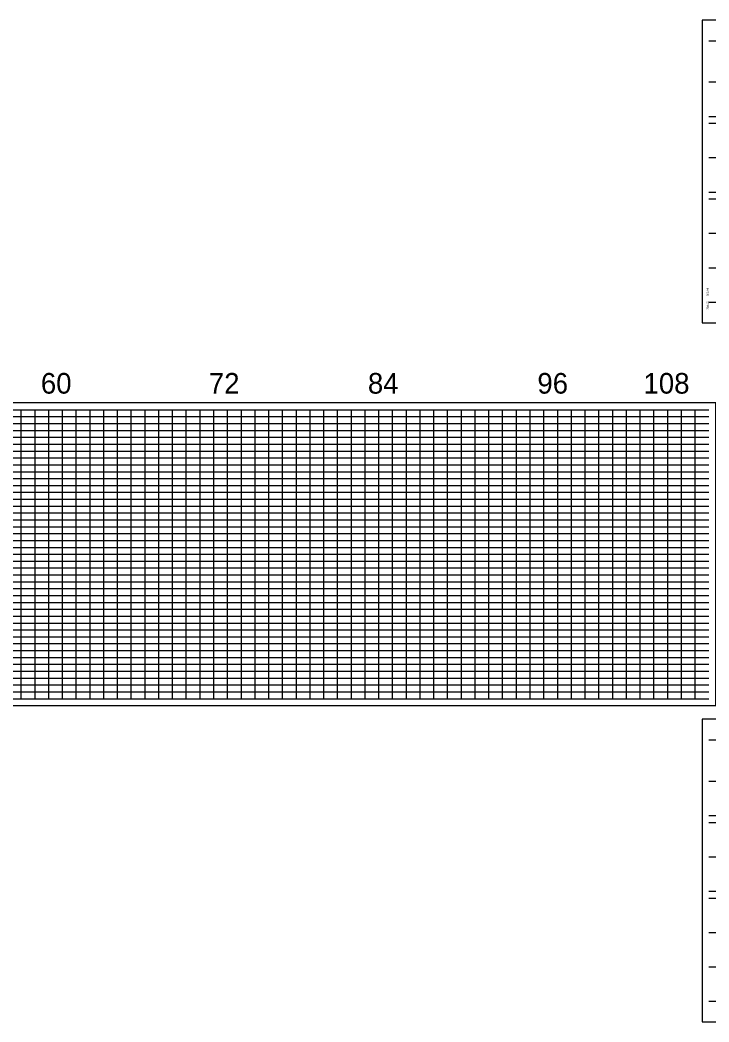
# Model space of a CAD drawing. Extents: x 1873632 to 1926512, y 813126 to 836257.
# Drawn here: x 1897209 to 1899713, y 823217 to 826858 of the extents above; entities that cross this region are included whole.
import ezdxf

# ---------------------------------------------------------------- set-up
doc = ezdxf.new("R2010")
doc.units = 0
for name, color, linetype in [('RD_DDB_StripGrade', 7, 'Continuous'), ('RD_PD_WallFill', 7, 'Continuous'), ('RD_SHT_IplotShp', 7, 'Continuous')]:
    doc.layers.add(name, color=color, linetype=linetype)

msp = doc.modelspace()

# ---------------------------------------------------------------- linework, layer by layer
at = {"layer": 'RD_PD_WallFill'}
for p, q in [((1899713.1, 826783.1), (1899763.1, 826783.1)), ((1899713.1, 826783.1), (1899763.1, 826783.1)), ((1899713.1, 826633.1), (1905063.1, 826633.1)), ((1899713.1, 826508.1), (1905063.1, 826508.1)), ((1899713.1, 826483.1), (1905063.1, 826483.1)), ((1899713.1, 826358.1), (1905063.1, 826358.1)), ((1899713.1, 826233.1), (1905063.1, 826233.1)), ((1899713.1, 826208.1), (1905063.1, 826208.1)), ((1899713.1, 826083.1), (1905063.1, 826083.1)), ((1899713.1, 825958.1), (1905063.1, 825958.1)), ((1899713.1, 825833.1), (1905063.1, 825833.1)), ((1894363.1, 825441.6), (1899713.1, 825441.6)), ((1897213.1, 824391.6), (1897213.1, 825441.6)), ((1897213.1, 824391.6), (1897213.1, 825441.6)), ((1897263.1, 824391.6), (1897263.1, 825441.6)), ((1897263.1, 824391.6), (1897263.1, 825441.6)), ((1897313.1, 824391.6), (1897313.1, 825441.6)), ((1897313.1, 824391.6), (1897313.1, 825441.6)), ((1897363.1, 824391.6), (1897363.1, 825441.6)), ((1897363.1, 824391.6), (1897363.1, 825441.6)), ((1897413.1, 824391.6), (1897413.1, 825441.6)), ((1897413.1, 824391.6), (1897413.1, 825441.6)), ((1897463.1, 824391.6), (1897463.1, 825441.6)), ((1897463.1, 824391.6), (1897463.1, 825441.6)), ((1897513.1, 824391.6), (1897513.1, 825441.6)), ((1897513.1, 824391.6), (1897513.1, 825441.6)), ((1897563.1, 824391.6), (1897563.1, 825441.6)), ((1897563.1, 824391.6), (1897563.1, 825441.6)), ((1897613.1, 824391.6), (1897613.1, 825441.6)), ((1897613.1, 824391.6), (1897613.1, 825441.6)), ((1897663.1, 824391.6), (1897663.1, 825441.6)), ((1897663.1, 824391.6), (1897663.1, 825441.6)), ((1897713.1, 824391.6), (1897713.1, 825441.6)), ((1897713.1, 824391.6), (1897713.1, 825441.6)), ((1897763.1, 824391.6), (1897763.1, 825441.6)), ((1897763.1, 824391.6), (1897763.1, 825441.6)), ((1897813.1, 824391.6), (1897813.1, 825441.6)), ((1897813.1, 824391.6), (1897813.1, 825441.6)), ((1897863.1, 824391.6), (1897863.1, 825441.6)), ((1897863.1, 824391.6), (1897863.1, 825441.6)), ((1897913.1, 824391.6), (1897913.1, 825441.6)), ((1897913.1, 824391.6), (1897913.1, 825441.6)), ((1897963.1, 824391.6), (1897963.1, 825441.6)), ((1897963.1, 824391.6), (1897963.1, 825441.6)), ((1898013.1, 824391.6), (1898013.1, 825441.6)), ((1898013.1, 824391.6), (1898013.1, 825441.6)), ((1898063.1, 824391.6), (1898063.1, 825441.6)), ((1898063.1, 824391.6), (1898063.1, 825441.6)), ((1898113.1, 824391.6), (1898113.1, 825441.6)), ((1898113.1, 824391.6), (1898113.1, 825441.6)), ((1898163.1, 824391.6), (1898163.1, 825441.6)), ((1898163.1, 824391.6), (1898163.1, 825441.6)), ((1898213.1, 824391.6), (1898213.1, 825441.6)), ((1898213.1, 824391.6), (1898213.1, 825441.6)), ((1898263.1, 824391.6), (1898263.1, 825441.6)), ((1898263.1, 824391.6), (1898263.1, 825441.6)), ((1898313.1, 824391.6), (1898313.1, 825441.6)), ((1898313.1, 824391.6), (1898313.1, 825441.6)), ((1898363.1, 824391.6), (1898363.1, 825441.6)), ((1898363.1, 824391.6), (1898363.1, 825441.6)), ((1898413.1, 824391.6), (1898413.1, 825441.6)), ((1898413.1, 824391.6), (1898413.1, 825441.6)), ((1898463.1, 824391.6), (1898463.1, 825441.6)), ((1898463.1, 824391.6), (1898463.1, 825441.6)), ((1898513.1, 824391.6), (1898513.1, 825441.6)), ((1898513.1, 824391.6), (1898513.1, 825441.6)), ((1898563.1, 824391.6), (1898563.1, 825441.6)), ((1898563.1, 824391.6), (1898563.1, 825441.6)), ((1898613.1, 824391.6), (1898613.1, 825441.6)), ((1898613.1, 824391.6), (1898613.1, 825441.6)), ((1898663.1, 824391.6), (1898663.1, 825441.6)), ((1898663.1, 824391.6), (1898663.1, 825441.6)), ((1898713.1, 824391.6), (1898713.1, 825441.6)), ((1898713.1, 824391.6), (1898713.1, 825441.6)), ((1898763.1, 824391.6), (1898763.1, 825441.6)), ((1898763.1, 824391.6), (1898763.1, 825441.6)), ((1898813.1, 824391.6), (1898813.1, 825441.6)), ((1898813.1, 824391.6), (1898813.1, 825441.6)), ((1898863.1, 824391.6), (1898863.1, 825441.6)), ((1898863.1, 824391.6), (1898863.1, 825441.6)), ((1898913.1, 824391.6), (1898913.1, 825441.6)), ((1898913.1, 824391.6), (1898913.1, 825441.6)), ((1898963.1, 824391.6), (1898963.1, 825441.6)), ((1898963.1, 824391.6), (1898963.1, 825441.6)), ((1899013.1, 824391.6), (1899013.1, 825441.6)), ((1899013.1, 824391.6), (1899013.1, 825441.6)), ((1899063.1, 824391.6), (1899063.1, 825441.6)), ((1899063.1, 824391.6), (1899063.1, 825441.6)), ((1899113.1, 824391.6), (1899113.1, 825441.6)), ((1899113.1, 824391.6), (1899113.1, 825441.6)), ((1899163.1, 824391.6), (1899163.1, 825441.6)), ((1899163.1, 824391.6), (1899163.1, 825441.6)), ((1899213.1, 824391.6), (1899213.1, 825441.6)), ((1899213.1, 824391.6), (1899213.1, 825441.6)), ((1899263.1, 824391.6), (1899263.1, 825441.6)), ((1899263.1, 824391.6), (1899263.1, 825441.6)), ((1899313.1, 824391.6), (1899313.1, 825441.6)), ((1899313.1, 824391.6), (1899313.1, 825441.6)), ((1899363.1, 824391.6), (1899363.1, 825441.6)), ((1899363.1, 824391.6), (1899363.1, 825441.6)), ((1899413.1, 824391.6), (1899413.1, 825441.6)), ((1899413.1, 824391.6), (1899413.1, 825441.6)), ((1899463.1, 824391.6), (1899463.1, 825441.6)), ((1899463.1, 824391.6), (1899463.1, 825441.6)), ((1899513.2, 824391.6), (1899513.1, 825441.6)), ((1899513.2, 824391.6), (1899513.1, 825441.6)), ((1899563.1, 824391.6), (1899563.2, 825441.6)), ((1899563.1, 824391.6), (1899563.2, 825441.6)), ((1899613.1, 824391.6), (1899613.1, 825441.6)), ((1899613.1, 824391.6), (1899613.1, 825441.6)), ((1899663.1, 824391.6), (1899663.1, 825441.6)), ((1899663.1, 824391.6), (1899663.1, 825441.6)), ((1894813.1, 825416.6), (1899713.1, 825416.6)), ((1894813.1, 825416.6), (1899713.1, 825416.6)), ((1894813.1, 825391.6), (1899713.1, 825391.6)), ((1894813.1, 825366.6), (1899713.1, 825366.6)), ((1894813.1, 825341.6), (1899713.1, 825341.6)), ((1894813.1, 825316.6), (1899713.1, 825316.6)), ((1894363.1, 825291.6), (1899713.1, 825291.6)), ((1894363.1, 825266.6), (1899713.1, 825266.6)), ((1894363.1, 825241.6), (1899713.1, 825241.6)), ((1894363.1, 825216.6), (1899713.1, 825216.6)), ((1894363.1, 825191.6), (1899713.1, 825191.6)), ((1894363.1, 825166.6), (1899713.1, 825166.6)), ((1894363.1, 825141.6), (1899713.1, 825141.6)), ((1894363.1, 825116.6), (1899713.1, 825116.6)), ((1894363.1, 825091.6), (1899713.1, 825091.6)), ((1894363.1, 825066.6), (1899713.1, 825066.6)), ((1894363.1, 825041.6), (1899713.1, 825041.6)), ((1894363.1, 825016.6), (1899713.1, 825016.6)), ((1894363.1, 824991.6), (1899713.1, 824991.6)), ((1894363.1, 824966.6), (1899713.1, 824966.6)), ((1894363.1, 824941.6), (1899713.1, 824941.6)), ((1894363.1, 824916.6), (1899713.1, 824916.6)), ((1894363.1, 824891.6), (1899713.1, 824891.6)), ((1894363.1, 824866.6), (1899713.1, 824866.6)), ((1894363.1, 824841.6), (1899713.1, 824841.6)), ((1894363.1, 824816.6), (1899713.1, 824816.6)), ((1894363.1, 824791.6), (1899713.1, 824791.6)), ((1894363.1, 824766.6), (1899713.1, 824766.6)), ((1894363.1, 824741.6), (1899713.1, 824741.6)), ((1894363.1, 824716.6), (1899713.1, 824716.6)), ((1894363.1, 824691.6), (1899713.1, 824691.6)), ((1894363.1, 824666.6), (1899713.1, 824666.6)), ((1894363.1, 824641.6), (1899713.1, 824641.6)), ((1894363.1, 824616.6), (1899713.1, 824616.6)), ((1894363.1, 824591.6), (1899713.1, 824591.6)), ((1894363.1, 824566.6), (1899713.1, 824566.6)), ((1894363.1, 824541.6), (1899713.1, 824541.6)), ((1894363.1, 824516.6), (1899713.1, 824516.6)), ((1894363.1, 824491.6), (1899713.1, 824491.6)), ((1894363.1, 824466.6), (1899713.1, 824466.6)), ((1894363.1, 824441.6), (1899713.1, 824441.6)), ((1894363.1, 824416.6), (1899713.1, 824416.6)), ((1894363.1, 824391.6), (1899713.1, 824391.6)), ((1894363.1, 824391.6), (1899713.1, 824391.6)), ((1899713.1, 824241.6), (1899763.1, 824241.6)), ((1899713.1, 824241.6), (1899763.1, 824241.6)), ((1899713.1, 824091.6), (1905063.1, 824091.6)), ((1899713.1, 823966.6), (1905063.1, 823966.6)), ((1899713.1, 823941.6), (1905063.1, 823941.6)), ((1899713.1, 823816.6), (1905063.1, 823816.6)), ((1899713.1, 823691.6), (1905063.1, 823691.6)), ((1899713.1, 823666.6), (1905063.1, 823666.6)), ((1899713.1, 823541.6), (1905063.1, 823541.6)), ((1899713.1, 823416.6), (1905063.1, 823416.6)), ((1899713.1, 823291.6), (1905063.1, 823291.6))]:
    msp.add_line(p, q, dxfattribs=at)
at = {"layer": 'RD_SHT_IplotShp'}
for points in [[(1899688.1, 825758.1), (1905088.1, 825758.1), (1905088.1, 826858.1), (1899688.1, 826858.1)], [(1894338.1, 824366.6), (1899738.1, 824366.6), (1899738.1, 825466.6), (1894338.1, 825466.6)], [(1899688.1, 823216.6), (1905088.1, 823216.6), (1905088.1, 824316.6), (1899688.1, 824316.6)]]:
    msp.add_lwpolyline(points, close=True, dxfattribs=at)

# ---------------------------------------------------------------- texts
at = {"layer": 'RD_DDB_StripGrade'}
for s, p in [('303.99', (1899712.1, 825854.9)), ('304.45', (1899712.1, 825805.7))]:
    msp.add_text(s, height=7, rotation=90, dxfattribs=at).set_placement(p)
at = {"layer": 'RD_PD_WallFill'}
for s, p in [('60', (1897284.3, 825500.3)), ('60', (1897284.3, 825500.3)), ('72', (1897895, 825500.3)), ('72', (1897895, 825500.3)), ('84', (1898473.2, 825500.3)), ('84', (1898473.2, 825500.3)), ('96', (1899089.3, 825500.3)), ('96', (1899089.3, 825500.3)), ('108', (1899475.1, 825500.3))]:
    msp.add_text(s, height=75, dxfattribs=at).set_placement(p)

doc.saveas('drawing.dxf')
